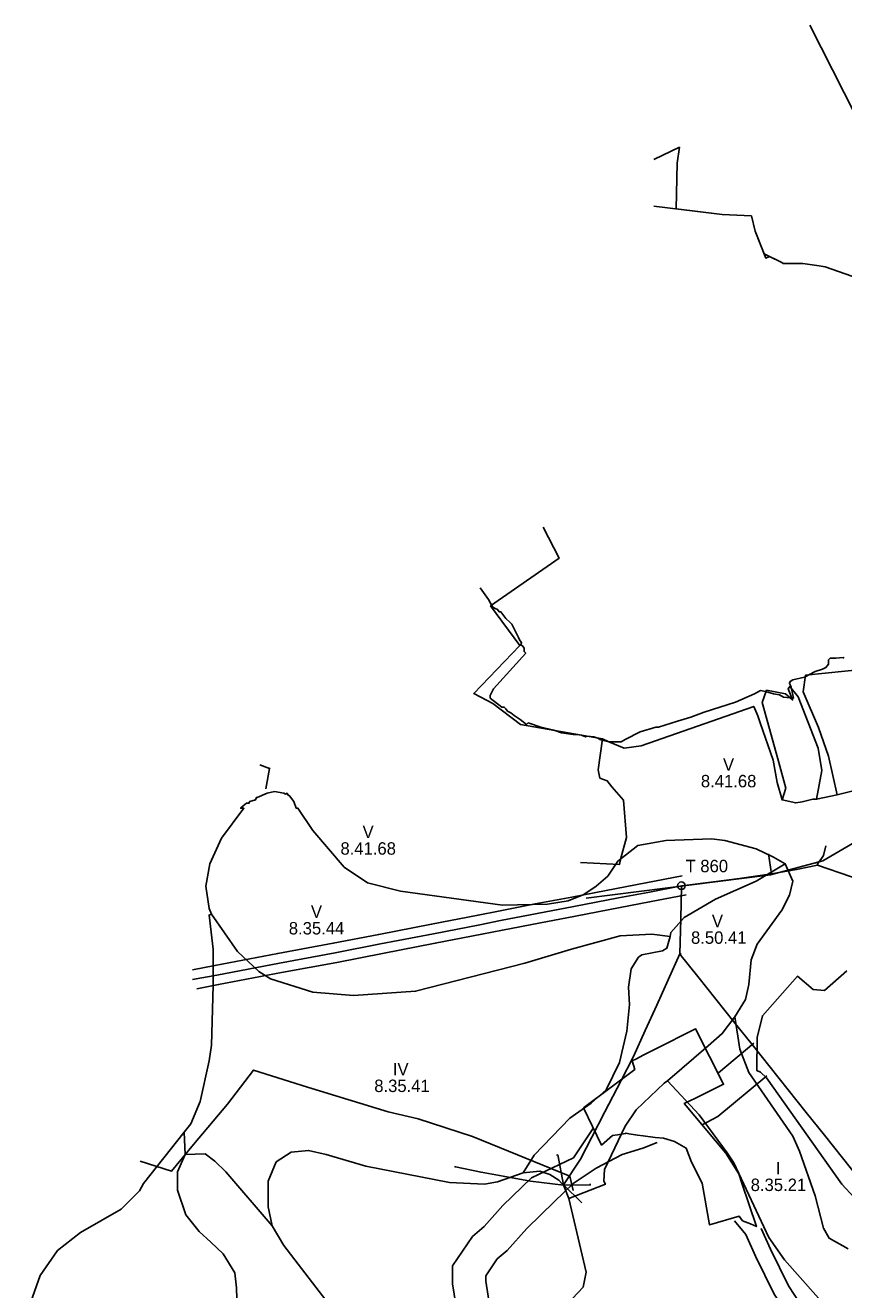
# Model space of a CAD drawing. Extents: x -694504 to -690518, y -983661 to -978958.
# Drawn here: x -693662 to -692675, y -980583 to -979057 of the extents above; entities that cross this region are included whole.
import ezdxf

# ---------------------------------------------------------------- set-up
doc = ezdxf.new("R2010")
doc.units = 0
for name, color, linetype in [('BPEJ', 7, 'Continuous'), ('chráněné ložiskové území', 7, 'Continuous'), ('lokální biocentra', 7, 'Continuous'), ('lokální biokoridory', 7, 'Continuous'), ('nadregionální biokoridor', 7, 'Continuous'), ('Natura 2000', 7, 'Continuous'), ('ochranné pásmo vedení', 7, 'Continuous'), ('regionální biocentrum', 7, 'Continuous'), ('trafostanice', 7, 'Continuous'), ('třídy přednosti v ochraně ZP', 7, 'Continuous'), ('vedení NN', 7, 'Continuous'), ('vedení VN 35kV', 7, 'Continuous'), ('vodovodní řad', 7, 'Continuous')]:
    doc.layers.add(name, color=color, linetype=linetype)

msp = doc.modelspace()

# ---------------------------------------------------------------- linework, layer by layer
at = {"layer": 'BPEJ'}
for points in [[(-693113.4, -979735.8), (-693103.4, -979749.8), (-693098.4, -979758.8), (-693095.4, -979760.8), (-693092.4, -979761.8), (-693090.4, -979764.8), (-693088.4, -979764.8), (-693082.4, -979772.8), (-693077.4, -979777.8), (-693075.4, -979779.8), (-693067.4, -979795.8), (-693066.4, -979797.8), (-693065.4, -979799.8), (-693063.4, -979801.8), (-693064.4, -979804.8), (-693062.4, -979805.8), (-693060.4, -979808.8), (-693060.4, -979812.8), (-693058.4, -979814.8), (-693097.4, -979857.8), (-693101.4, -979865.8), (-693101.4, -979868.8), (-693087.4, -979879.8), (-693084.4, -979879.8), (-693082.4, -979881.8), (-693080.4, -979884.8), (-693076.4, -979886.8), (-693072.4, -979889.8), (-693065.4, -979894.8), (-693057.4, -979900.8), (-693055.4, -979898.8), (-693040.4, -979903.8), (-693024.4, -979907.8), (-693015.4, -979910.8), (-693001.4, -979912.8), (-692997.4, -979912.8), (-692991.4, -979913.8), (-692986.4, -979915.8), (-692984.4, -979914.8), (-692976.4, -979915.8), (-692970.4, -979917.8), (-692969.4, -979918.8), (-692958.4, -979921.8), (-692943.4, -979921.8), (-692938.4, -979918.8), (-692920.4, -979909.8), (-692901.4, -979903.8), (-692898.4, -979903.8), (-692875.4, -979896.8), (-692859.4, -979891.8), (-692843.4, -979885.8), (-692805.4, -979873.8), (-692782.4, -979863.8), (-692775.4, -979859.8), (-692769.4, -979860.8), (-692759.4, -979863.8), (-692752.4, -979864.8), (-692747.4, -979867.8), (-692735.4, -979868.8), (-692738.4, -979855.8), (-692740.4, -979850.8), (-692739.4, -979848.8), (-692736.4, -979846.8), (-692722.4, -979843.8), (-692709.4, -979836.8), (-692700.4, -979833.8), (-692696.4, -979831.8), (-692693.4, -979827.8), (-692693.4, -979822.8), (-692691.4, -979820.8), (-692684.4, -979820.8), (-692675.4, -979819.8), (-692674.4, -979820.8)], [(-692667.4, -980635.8), (-692746.4, -980546.8), (-692765.4, -980519.8), (-692807.4, -980429.8), (-692815.4, -980417.8), (-692849.4, -980371.8), (-692887.4, -980330.8), (-692838.4, -980288.8), (-692821.4, -980273.8), (-692806.4, -980253.8), (-692800.4, -980292.8), (-692789.4, -980320.8), (-692736.4, -980397.8), (-692728.4, -980415.8), (-692709.4, -980469.8), (-692699.4, -980508.8), (-692692.4, -980520.8), (-692669.4, -980533.8)], [(-693014.4, -980606.8), (-692989.4, -980579.8), (-692985.4, -980561.8), (-693006.4, -980472.8), (-692962.4, -980455.8), (-692964.4, -980451.8), (-692963.4, -980437.8), (-692938.4, -980385.8), (-692925.4, -980365.8), (-692891.4, -980333.8), (-692887.4, -980330.8), (-692849.4, -980371.8), (-692815.4, -980417.8), (-692807.4, -980429.8), (-692765.4, -980519.8), (-692746.4, -980546.8), (-692667.4, -980635.8)], [(-693655.4, -980597.8), (-693644.4, -980565.8), (-693623.4, -980535.8), (-693595.4, -980513.8), (-693546.4, -980485.8), (-693524.4, -980463.8), (-693519.4, -980454.8), (-693470.4, -980392.8), (-693469.4, -980419.8), (-693469.4, -980419.8)], [(-693290.4, -980607.8), (-693350.4, -980529.8), (-693364.4, -980505.8), (-693369.4, -980482.8), (-693369.4, -980451.8), (-693359.4, -980428.8), (-693341.4, -980416.8), (-693320.4, -980414.8), (-693299.4, -980419.8), (-693251.4, -980433.8), (-693150.4, -980453.8), (-693108.4, -980455.8), (-693092.4, -980452.8), (-693061.4, -980441.8), (-693041.4, -980439.8), (-693029.4, -980443.8), (-693018.4, -980450.8), (-693012.4, -980457.8), (-693006.4, -980472.8), (-692985.4, -980561.8), (-692989.4, -980579.8), (-693014.4, -980606.8)], [(-693405.4, -980647.8), (-693407.4, -980580.8), (-693409.4, -980562.8), (-693423.4, -980539.8), (-693438.4, -980525.8), (-693452.4, -980512.8), (-693468.4, -980492.8), (-693478.4, -980462.8), (-693478.4, -980440.8), (-693469.4, -980419.8), (-693445.4, -980418.8), (-693433.4, -980427.8), (-693420.4, -980440.8), (-693364.4, -980505.8), (-693364.4, -980505.8), (-693350.4, -980529.8), (-693290.4, -980607.8)], [(-693469.4, -980419.8), (-693478.4, -980440.8), (-693478.4, -980462.8), (-693468.4, -980492.8), (-693452.4, -980512.8), (-693438.4, -980525.8), (-693423.4, -980539.8), (-693409.4, -980562.8), (-693407.4, -980580.8), (-693405.4, -980647.8)]]:
    msp.add_lwpolyline(points, dxfattribs=at)
for points in [[(-692745.4, -980068.8), (-692780.4, -980089.8), (-692829.4, -980111.8), (-692867.4, -980133.8), (-692883.4, -980151.8), (-692884.4, -980156.8), (-692906.4, -980153.8), (-692944.4, -980155.8), (-693003.4, -980171.8), (-693059.4, -980188.8), (-693191.4, -980222.8), (-693266.4, -980227.8), (-693315.4, -980223.8), (-693366.4, -980207.8), (-693380.4, -980198.8), (-693406.4, -980174.8), (-693437.4, -980129.8), (-693440.4, -980122.8), (-693444.4, -980095.8), (-693439.4, -980068.8), (-693425.4, -980037.8), (-693398.4, -980001.8), (-693401.4, -980001.8), (-693402.4, -980001.8), (-693399.4, -979998.8), (-693395.4, -979995.8), (-693392.4, -979995.8), (-693391.4, -979993.8), (-693384.4, -979991.8), (-693383.4, -979988.8), (-693382.4, -979988.8), (-693370.4, -979983.8), (-693361.4, -979981.8), (-693350.4, -979983.8), (-693348.4, -979984.8), (-693346.4, -979983.8), (-693345.4, -979985.8), (-693343.4, -979986.8), (-693338.4, -979993.8), (-693335.4, -980001.8), (-693334.4, -980001.8), (-693333.4, -980001.8), (-693315.4, -980028.8), (-693277.4, -980072.8), (-693249.4, -980091.8), (-693209.4, -980101.8), (-693086.4, -980118.8), (-693032.4, -980117.8), (-693007.4, -980113.8), (-692988.4, -980105.8), (-692973.4, -980095.8), (-692959.4, -980083.8), (-692947.4, -980065.8), (-692923.4, -980046.8), (-692889.4, -980040.8), (-692834.4, -980038.8), (-692818.4, -980040.8), (-692780.4, -980050.8), (-692759.4, -980060.8), (-692745.4, -980068.8)], [(-692806.4, -980253.8), (-692821.4, -980273.8), (-692838.4, -980288.8), (-692887.4, -980330.8), (-692891.4, -980333.8), (-692925.4, -980365.8), (-692938.4, -980385.8), (-692963.4, -980437.8), (-692964.4, -980451.8), (-692962.4, -980455.8), (-693006.4, -980472.8), (-693012.4, -980457.8), (-693018.4, -980450.8), (-693029.4, -980443.8), (-693041.4, -980439.8), (-693061.4, -980441.8), (-693048.4, -980420.8), (-693005.4, -980375.8), (-692979.4, -980357.8), (-692961.4, -980341.8), (-692945.4, -980308.8), (-692936.4, -980270.8), (-692933.4, -980238.8), (-692934.4, -980217.8), (-692931.4, -980195.8), (-692922.4, -980181.8), (-692918.4, -980178.8), (-692893.4, -980173.8), (-692888.4, -980170.8), (-692884.4, -980156.8), (-692883.4, -980151.8), (-692867.4, -980133.8), (-692829.4, -980111.8), (-692780.4, -980089.8), (-692745.4, -980068.8), (-692736.4, -980089.8), (-692740.4, -980106.8), (-692749.4, -980124.8), (-692779.4, -980165.8), (-692786.4, -980184.8), (-692789.4, -980214.8), (-692793.4, -980232.8), (-692806.4, -980253.8)], [(-692884.4, -980156.8), (-692888.4, -980170.8), (-692893.4, -980173.8), (-692918.4, -980178.8), (-692922.4, -980181.8), (-692931.4, -980195.8), (-692934.4, -980217.8), (-692933.4, -980238.8), (-692936.4, -980270.8), (-692945.4, -980308.8), (-692961.4, -980341.8), (-692979.4, -980357.8), (-693005.4, -980375.8), (-693048.4, -980420.8), (-693061.4, -980441.8), (-693092.4, -980452.8), (-693108.4, -980455.8), (-693150.4, -980453.8), (-693251.4, -980433.8), (-693299.4, -980419.8), (-693320.4, -980414.8), (-693341.4, -980416.8), (-693359.4, -980428.8), (-693369.4, -980451.8), (-693369.4, -980482.8), (-693364.4, -980505.8), (-693420.4, -980440.8), (-693433.4, -980427.8), (-693445.4, -980418.8), (-693469.4, -980419.8), (-693470.4, -980392.8), (-693462.4, -980382.8), (-693451.4, -980355.8), (-693440.4, -980306.8), (-693437.4, -980287.8), (-693435.4, -980215.8), (-693435.4, -980171.8), (-693440.4, -980130.8), (-693437.4, -980129.8), (-693406.4, -980174.8), (-693380.4, -980198.8), (-693366.4, -980207.8), (-693315.4, -980223.8), (-693266.4, -980227.8), (-693191.4, -980222.8), (-693059.4, -980188.8), (-693003.4, -980171.8), (-692944.4, -980155.8), (-692906.4, -980153.8), (-692884.4, -980156.8)]]:
    msp.add_lwpolyline(points, close=True, dxfattribs=at)
at = {"layer": 'chráněné ložiskové území'}
msp.add_lwpolyline([(-691332.6, -980056.6), (-691597, -980399.4), (-692068.6, -980332.4), (-692715.6, -979056.8)], dxfattribs=at)
at = {"layer": 'lokální biocentra'}
msp.add_lwpolyline([(-692671, -980198.1), (-692698, -980221.7), (-692711.9, -980220.7), (-692730.6, -980204.7), (-692772.9, -980252.4), (-692779.2, -980278.4), (-692779.7, -980318.6), (-692775.2, -980320.6), (-692768, -980327.1), (-692677.1, -980455.5), (-692662.1, -980471.8)], dxfattribs=at)
msp.add_lwpolyline([(-692989, -980363.3), (-692966.9, -980408.5), (-692953.8, -980396.7), (-692947.7, -980395.9), (-692938.3, -980394.3), (-692937.5, -980394.2), (-692934.2, -980394.7), (-692926.2, -980396), (-692923.8, -980396.3), (-692917, -980397.3), (-692902.5, -980399.1), (-692892.3, -980400.2), (-692879.1, -980404), (-692864.9, -980412.1), (-692858.4, -980429.1), (-692845.6, -980454.5), (-692837, -980504.5), (-692801, -980494.3), (-692796.8, -980499.8), (-692787.2, -980503.3), (-692780.3, -980506.8), (-692797.7, -980454.5), (-692801.4, -980443.2), (-692817.3, -980418), (-692854.7, -980373.7), (-692865, -980361), (-692867.2, -980358.3), (-692853.8, -980351.7), (-692819.9, -980335), (-692853.6, -980268.3), (-692903, -980293.2), (-692916.7, -980300.1), (-692924.9, -980304.2), (-692930.2, -980306.9), (-692926.7, -980317.2)], close=True, dxfattribs=at)
at = {"layer": 'lokální biokoridory'}
for points in [[(-692806.8, -980499.7), (-692792.9, -980516.4), (-692781.4, -980542.5), (-692758.8, -980588.4), (-692729.8, -980632.7), (-692719.8, -980643.6), (-692712.7, -980665.5), (-692705.5, -980685.4), (-692700.4, -980701.7), (-692702.8, -980718.6), (-692702.1, -980722.4)], [(-692682.3, -980716.3), (-692680, -980700), (-692686.5, -980679), (-692693.8, -980659), (-692702.1, -980633.3), (-692714, -980620.3), (-692741.4, -980578.5), (-692763.2, -980534), (-692774.3, -980509), (-692774.3, -980509)]]:
    msp.add_lwpolyline(points, dxfattribs=at)
at = {"layer": 'nadregionální biokoridor'}
msp.add_line((-692783.2, -980285.5), (-692825.8, -980321.2), dxfattribs=at)
for points in [[(-692845.7, -980384), (-692826.6, -980373.9), (-692826.6, -980373.9), (-692767.7, -980324.7)], [(-692976.9, -980387.7), (-693001, -980423.8), (-693051.7, -980447.9), (-693086.3, -980481.5), (-693108.8, -980506.9), (-693122.8, -980518.8), (-693146.8, -980554.1), (-693146.8, -980575.9), (-693138.4, -980628.3), (-693165.6, -980702.1), (-693190.1, -980705.8), (-693196.3, -980766.6), (-693215.3, -980804.5), (-693215.5, -980802.6), (-693218.4, -980803.2), (-693225.6, -980825.7), (-693359.1, -980854.7), (-693655.1, -980918.9), (-693662.2, -980917.2), (-693662.2, -980917.2), (-693662.2, -980917.2)], [(-693202.4, -980861.1), (-693194.2, -980859.3), (-693187.2, -980837.3), (-693172.1, -980833.9), (-693174.5, -980813), (-693157.3, -980777.9), (-693153.5, -980740.7), (-693138.6, -980738.5), (-693130.4, -980722.2), (-693097.2, -980632.3), (-693106.8, -980572.7), (-693106.8, -980566.4), (-693092.8, -980545.8), (-693080.8, -980535.6), (-693057.3, -980509.1), (-693023.9, -980476.7), (-693001.2, -980454.9), (-692973.6, -980436.5), (-692942.1, -980419.8), (-692917.3, -980412.2), (-692899.8, -980405.5)]]:
    msp.add_lwpolyline(points, dxfattribs=at)
at = {"layer": 'Natura 2000'}
for points in [[(-692903.9, -979275.1), (-692821.5, -979285), (-692786.3, -979286.8), (-692781.8, -979305.1), (-692768.9, -979337.8), (-692764.6, -979335.9), (-692749.7, -979343.3), (-692748.1, -979344.2), (-692724.1, -979344.2), (-692704.6, -979347.3), (-692697.2, -979348.4), (-692657, -979362.5)], [(-692626, -979831.5), (-692720.8, -979841.1), (-692723.9, -979861.2), (-692705.5, -979904.3), (-692693.2, -979939.1), (-692682.8, -979985.7), (-692707.7, -979990.9), (-692701.2, -979956.1), (-692705.8, -979929.2), (-692730, -979867.3), (-692739.9, -979854.9), (-692742, -979857.9), (-692736.6, -979871.1), (-692745.1, -979863.8), (-692768, -979859.4), (-692773.4, -979874.4), (-692754.4, -979942.3), (-692744.6, -979977.8), (-692749.2, -979991.9), (-692755.1, -979970.7), (-692759.9, -979943.9), (-692775.7, -979898.8), (-692778.7, -979890.3), (-692783.5, -979879), (-692919.1, -979926.6), (-692939.8, -979929.2), (-692958.2, -979921.5), (-692965.8, -979918.2), (-692971, -979955.6), (-692969.1, -979965.4), (-692960.1, -979968.9), (-692954.8, -979975.9), (-692940.6, -979992.3), (-692937.1, -980037.3), (-692943.9, -980062.2), (-692945.3, -980069.6), (-692992.4, -980067.4)]]:
    msp.add_lwpolyline(points, dxfattribs=at)
at = {"layer": 'ochranné pásmo vedení'}
for points in [[(-692869.8, -980083.3), (-692913.6, -980091.9), (-692948.8, -980098.6), (-693002.8, -980109), (-693047, -980117.4), (-693091.2, -980125.9), (-693116, -980130.8), (-693172.1, -980141.9), (-693235.8, -980154.1), (-693290.7, -980164.9), (-693357.6, -980177.1), (-693433.5, -980191.7), (-693460.6, -980196.8)], [(-693455.3, -980219.7), (-693429.1, -980214.7), (-693353.3, -980200.2), (-693286.3, -980188), (-693231.4, -980177.2), (-693167.6, -980164.9), (-693111.4, -980153.9), (-693086.7, -980149), (-693042.6, -980140.5), (-692998.4, -980132), (-692944.4, -980121.7), (-692909.1, -980115), (-692864.8, -980106.3)]]:
    msp.add_lwpolyline(points, dxfattribs=at)
at = {"layer": 'regionální biocentrum'}
for points in [[(-692657, -979362.5), (-692697.2, -979348.4), (-692704.6, -979347.3), (-692724.1, -979344.2), (-692748.1, -979344.2), (-692749.7, -979343.3), (-692770.9, -979332.7), (-692781.8, -979305.1), (-692786.3, -979286.8), (-692821.5, -979285), (-692877, -979278.3), (-692875.8, -979223.4), (-692873, -979204.1), (-692904, -979218.8)], [(-693037.3, -979662.5), (-693018.2, -979700.1), (-693100.8, -979757.7), (-693065.5, -979805.6), (-693121.2, -979863.3), (-693098, -979875.6), (-693064.9, -979900.8), (-692965.8, -979918.2), (-692958.2, -979921.5), (-692939.8, -979929.2), (-692919.1, -979926.6), (-692783.5, -979879), (-692778.7, -979890.3), (-692775.7, -979898.8), (-692759.9, -979943.9), (-692755.1, -979970.7), (-692749.2, -979991.9), (-692732.7, -979995.5), (-692725, -979994.1), (-692712, -979990.9), (-692707.7, -979990.9), (-692682.8, -979985.7), (-692623.8, -979970.6)]]:
    msp.add_lwpolyline(points, dxfattribs=at)
at = {"layer": 'trafostanice'}
msp.add_ellipse((-692870.7, -980095.4), major_axis=(0, 4.66), ratio=0.997816, dxfattribs=at)
at = {"layer": 'vedení NN'}
msp.add_line((-693367.6, -979953.8), (-693379.4, -979949.3), dxfattribs=at)
for points in [[(-693367.6, -979953.8), (-693372.1, -979978.5)], [(-693367.6, -979953.8), (-693368.5, -979954.8)], [(-693367.6, -979953.8), (-693366.7, -979952.9)], [(-692706.4, -980069.3), (-692704.5, -980066), (-692702.7, -980063.7), (-692699.1, -980058.8), (-692696.6, -980047.2)], [(-692762, -980081.1), (-692765.8, -980056.9)], [(-692762, -980081.1), (-692732, -980075.6), (-692706.4, -980070.6)], [(-692706.4, -980070.6), (-692706.4, -980069.3)], [(-692706.4, -980070.6), (-692666.9, -980084.4), (-692632.2, -980095.3)], [(-692870.1, -980095.4), (-692832, -980090.8), (-692800.7, -980086.6), (-692762, -980081.1)], [(-692870.7, -980095.9), (-692871.4, -980135.3), (-692872.7, -980177.5)], [(-692870.7, -980096.6), (-692870.1, -980096.6), (-692870.1, -980095.4)], [(-692870.7, -980096.6), (-692870.5, -980096.6), (-692870.5, -980095.9), (-692870.7, -980095.9)], [(-692872.7, -980177.5), (-692886.6, -980208.8), (-692900.5, -980239.6), (-692914.3, -980270.3), (-692928.3, -980301.7), (-692943.3, -980330.6), (-692962.9, -980368.5), (-692978.8, -980399), (-692992.3, -980425.6), (-693012.9, -980456.4)], [(-692871.4, -980177.7), (-692871.4, -980177.5), (-692872.7, -980177.5)], [(-692871.4, -980177.7), (-692871.5, -980177.9), (-692872.7, -980177.9)], [(-692872.7, -980177.9), (-692850.9, -980205), (-692829.1, -980232.4), (-692807.3, -980259.8), (-692785.5, -980287.1), (-692763.7, -980314.5), (-692741.9, -980341.9), (-692720, -980369.2), (-692698.2, -980396.6), (-692676.4, -980424), (-692654.6, -980451.3)], [(-693012.9, -980456.4), (-693019.9, -980420.4), (-693021.5, -980420.8)], [(-693014.2, -980456.2), (-693014.3, -980456.4), (-693013, -980456.8), (-693052.7, -980452.1), (-693085.6, -980446.1), (-693112.4, -980441.3), (-693143.3, -980434.5), (-693144.6, -980434.3)], [(-693014.2, -980456.2), (-693014.1, -980456), (-693012.9, -980456.4)], [(-693012.9, -980456.4), (-692980.8, -980456.8), (-692980.8, -980455.1)], [(-693012.9, -980456.4), (-692990.9, -980478.1)]]:
    msp.add_lwpolyline(points, dxfattribs=at)
at = {"layer": 'vedení VN 35kV'}
msp.add_lwpolyline([(-692870.7, -980095.4), (-692911.3, -980103.5), (-692946.6, -980110.1), (-693000.6, -980120.5), (-693044.8, -980129), (-693089, -980137.5), (-693113.7, -980142.4), (-693169.9, -980153.4), (-693233.6, -980165.6), (-693288.5, -980176.4), (-693355.4, -980188.7), (-693431.3, -980203.2), (-693460.4, -980208.7)], dxfattribs=at)
at = {"layer": 'vodovodní řad'}
for points in [[(-692335.7, -980324.3), (-692362.6, -980352.1), (-692377.8, -980341.4), (-692400.1, -980322.6), (-692426.9, -980288.7), (-692437.7, -980270.8), (-692447.3, -980228.4), (-692459, -980163.2), (-692478.6, -980139.1), (-692496.5, -980120.3), (-692517.9, -980084.6), (-692534.9, -980067.6), (-692642, -980031.4), (-692700, -980065.3), (-692763.3, -980082.1), (-692985.5, -980110.3)], [(-693523.8, -980428), (-693485.9, -980440.1), (-693459.4, -980407.8), (-693418.1, -980359.2), (-693387, -980317.9), (-693321.9, -980338.5), (-693224.5, -980368.2), (-693188.2, -980376.9), (-693122.8, -980397.9), (-693005.4, -980446.1), (-693001.1, -980463.2)]]:
    msp.add_lwpolyline(points, dxfattribs=at)

# ---------------------------------------------------------------- texts
at = {"layer": 'trafostanice'}
msp.add_text('T 860', height=15, dxfattribs=at).set_placement((-692865.7, -980079.1))
at = {"layer": 'třídy přednosti v ochraně ZP'}
for s, p in [('V', (-692820.5, -979956.6)), ('8.41.68', (-692847.2, -979976.6)), ('V', (-693255.3, -980037.9)), ('8.41.68', (-693282, -980057.9)), ('V', (-693317.6, -980134.2)), ('8.35.44', (-693344.3, -980154.2)), ('V', (-692833.9, -980145.5)), ('8.50.41', (-692859.1, -980165.5)), ('IV', (-693218.8, -980324.4)), ('8.35.41', (-693241.2, -980344.4)), ('I', (-692756.8, -980443.9)), ('8.35.21', (-692787.1, -980463.9))]:
    msp.add_text(s, height=15, dxfattribs=at).set_placement(p)

doc.saveas('drawing.dxf')
